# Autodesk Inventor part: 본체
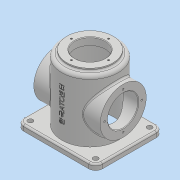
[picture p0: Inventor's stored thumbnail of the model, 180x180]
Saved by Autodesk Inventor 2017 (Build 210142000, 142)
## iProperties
Part Number: 본체
Material: 일반
Document SubType Name: Modeling
Designer: MRC
Density: 1 g/cm^3
Appearance: 기본값
Author: MRC
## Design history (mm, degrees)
sketch "스케치1"
  geometry: L1 (-70, -60)-(70, -60); L2 (70, -60)-(70, 60); L3 (70, 60)-(-70, 60); L4 (-70, 60)-(-70, -60); L5 (-70, -60)-(70, 60); L6 (70, -60)-(-70, 60); 1 further point
  constraints: 12 end point, 2 midpoint, 2 parallel, 1 horizontal, 1 perpendicular
  dimensions: "d0" = 140 distance of L3.end L2.end; "d1" = 120 distance of L2.end L1.end
extrude "돌출1" new body sketch "스케치1" distance "d2" = 10; taper "d3" = 0 deg
sketch "스케치2"
  geometry: C1 r 50 at (0, 0); 1 further point
  constraints: 1 centre point, 1 coincident
  dimensions: "d4" = 100 diameter of C1
extrude "돌출2" join sketch "스케치2" distance "d5" = 110; taper "d6" = 0 deg
sketch "스케치3"
  geometry: C1 r 50 at (0, 0) reference; C2 r 41 at (0, 0)
  constraints: 1 centre point, 1 coincident
  dimensions: "d7" = 82 diameter of C2
extrude "돌출3" join sketch "스케치3" distance "d8" = 5; taper "d9" = 0 deg
node "작업 평면1"
sketch "스케치4"
  geometry: L1 (-60, 0)-(60, 0) reference; C1 r 41 at (0, 60); 2 further points
  constraints: 1 centre point, 1 midpoint, 1 vertical alignment
  dimensions: "d11" = 60 distance from line of L1 C1.centre; "d12" = 82 diameter of C1
extrude "돌출4" join sketch "스케치4" stored distance "d13" = 5; taper "d14" = 0 deg
sketch "스케치5"
  geometry: C1 r 41 at (0, 0) reference; C2 r 27 at (0, 0); 1 further point
  constraints: 1 centre point, 1 coincident
  dimensions: "d15" = 54 diameter of C2
extrude "돌출5" cut sketch "스케치5" distance "d16" = 168; taper "d17" = 0 deg
sketch "스케치6"
  geometry: C1 r 27 at (0, 0) reference; 2 further points
  constraints: 1 vertical alignment
  dimensions: "d18" = 33 distance of C1.centre point (0, 33)
hole "구멍1" sketch "스케치6" at (0, 33) diameter "d19" = 3.242; stored, may be unused: countersink angle "d23" = 90 deg, drill point angle "d25" = 118 deg; dims "d20" = 8, "d21" = 4, "d22" = 2, "d24" = 10
sketch "스케치7"
  geometry: C1 r 42 at (0, 0); 1 further point
  constraints: 1 centre point, 1 coincident
  dimensions: "d29" = 84 diameter of C1
extrude "돌출6" cut sketch "스케치7" distance "d30" = 112; taper "d31" = 0 deg
sketch "스케치8"
  geometry: C1 r 41 at (0, 0) reference; C2 r 27 at (0, 0)
  constraints: 1 centre point, 1 coincident
  dimensions: "d32" = 54 diameter of C2
extrude "돌출7" cut sketch "스케치8" distance "d33" = 112; taper "d34" = 0 deg
sketch "스케치9"
  geometry: C1 r 27 at (0, 0) reference; 1 further point
  constraints: 1 vertical alignment
  dimensions: "d35" = 33 distance of C1.centre point (0, 33)
hole "구멍2" sketch "스케치9" at (0, 33) diameter "d36" = 3.242; stored, may be unused: countersink angle "d40" = 90 deg, drill point angle "d42" = 118 deg; dims "d37" = 8, "d38" = 4, "d39" = 2, "d41" = 10
fillet "모깎기1" dims "d46" = 12
fillet "모깎기2" dims "d47" = 6
fillet "모깎기3" dims "d48" = 3
chamfer "모따기1" distance "d49" = 1; stored, may be unused: second distance "d50" = 2, angle "d51" = 45 deg
sketch "스케치10"
  geometry: A1 r 9 centre (-58, -48) between (-67, -48) and (-58, -57) reference; A2 r 9 centre (58, -48) between (58, -57) and (67, -48) reference; A3 r 9 centre (58, 48) between (67, 48) and (58, 57) reference; A4 r 9 centre (-58, 48) between (-58, 57) and (-67, 48) reference
hole "구멍3" sketch "스케치10" at (-58, -48), (58, -48), (-58, 48), (58, 48) diameter "d52" = 9; stored, may be unused: countersink angle "d56" = 90 deg, drill point angle "d58" = 118 deg; dims "d53" = 8, "d54" = 4, "d55" = 2, "d57" = 10
node "작업 평면2"
sketch "스케치11"
  geometry: L1 (-58, -10)-(58, -10) reference; L2 (70, -10)-(58, -10) reference; 3 further points
  constraints: 1 midpoint, 1 vertical alignment, 1 other
  dimensions: "d62" = 66 distance from line of L2 point (0, 56)
feature "엠보싱1" sketch "스케치11" dims "d0" = 140, "d1" = 120, "d60" = 0.5, "d61" = 0
node "솔리드1"
pattern_circular "원형 패턴1" dims angle "d27" = 360 deg
mirror "미러1"
pattern_circular "원형 패턴2" dims angle "d44" = 360 deg
other parameters: "d10" = 59
